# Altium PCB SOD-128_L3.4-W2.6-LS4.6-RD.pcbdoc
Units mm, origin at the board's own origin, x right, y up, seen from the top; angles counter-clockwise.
Board outline 18.44 x 15.45 mm, 2 copper layers (Top Layer, Bottom Layer), stack 0 mm thick; 1 components, 0 nets, 2 pads, 0 vias.
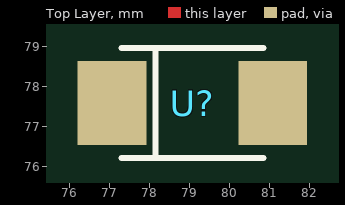
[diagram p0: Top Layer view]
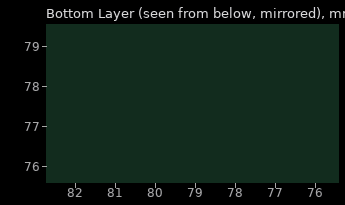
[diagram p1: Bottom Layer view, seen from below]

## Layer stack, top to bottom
Top Layer: signal copper (thickness not stored)
Bottom Layer: signal copper (thickness not stored)

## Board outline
88.29,69.85 69.85,69.85 69.85,85.302 88.29,85.302

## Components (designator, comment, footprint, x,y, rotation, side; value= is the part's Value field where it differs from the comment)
U? "" SOD-128_L3.4-W2.6-LS4.6-RD 79.07,77.576 r0 top

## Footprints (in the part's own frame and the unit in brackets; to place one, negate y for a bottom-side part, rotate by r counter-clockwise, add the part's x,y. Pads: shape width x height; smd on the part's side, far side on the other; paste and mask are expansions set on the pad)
SOD-128_L3.4-W2.6-LS4.6-RD [mm]
  rect 1.72x2.1 smd: 1(-2.01,0) 2(2.01,0)
  silkscreen extent -1.78,-1.38 1.78,1.38

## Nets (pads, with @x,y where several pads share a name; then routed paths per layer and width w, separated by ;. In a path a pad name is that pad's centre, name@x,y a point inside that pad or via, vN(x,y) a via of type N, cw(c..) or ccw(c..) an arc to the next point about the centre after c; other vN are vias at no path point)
pads on no net: U?.1 U?.2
